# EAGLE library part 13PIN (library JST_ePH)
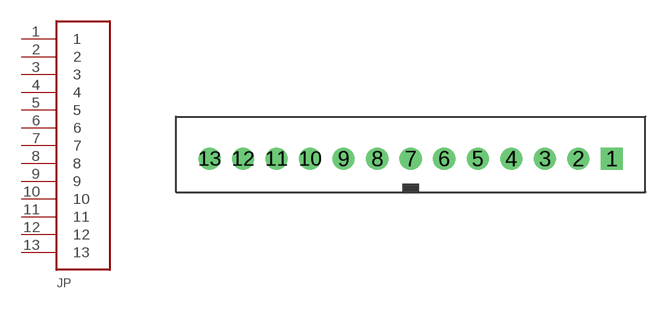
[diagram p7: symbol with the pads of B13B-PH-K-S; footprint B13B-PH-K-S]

Designator prefix JP

## 13PIN  [B13B-PH-K-S]
1  1
2  2
3  3
4  4
5  5
6  6
7  7
8  8
9  9
10  10
11  11
12  12
13  13

## Footprint B13B-PH-K-S (pad centres in mm)
drill 0.813 square: 1 12,0
drill 0.813 round: 2 10,0; 3 8,0; 4 6,0; 5 4,0; 6 2,0; 7 0,0; 8 -2,0; 9 -4,0; 10 -6,0; 11 -8,0; 12 -10,0; 13 -12,0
